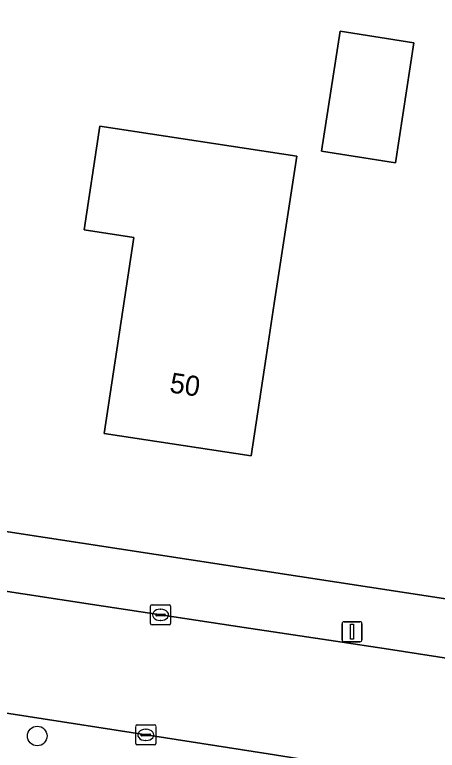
# Model space of a CAD drawing. Extents: x 161483 to 162250, y 379484 to 380833.
# Drawn here: x 161693.19 to 161714.27, y 380443.72 to 380480.35 of the extents above; entities that cross this region are included whole.
import ezdxf

# ---------------------------------------------------------------- set-up
doc = ezdxf.new("R2010")
doc.units = 0
for name, color, linetype in [('IMGEO_Boom', 7, 'Continuous'), ('IMGEO_Erf', 7, 'Continuous'), ('IMGEO_Kolk', 7, 'Continuous'), ('IMGEO_Lichtmast', 7, 'Continuous'), ('IMGEO_Pand', 7, 'Continuous'), ('IMGEO_Pand_nummerreeks', 7, 'Continuous'), ('IMGEO_Rijbaan_lokaal_open', 7, 'Continuous'), ('IMGEO_Voetpad_open', 7, 'Continuous')]:
    doc.layers.add(name, color=color, linetype=linetype)

msp = doc.modelspace()

# ---------------------------------------------------------------- linework, layer by layer
at = {"layer": 'IMGEO_Boom'}
msp.add_circle((161694.317, 380444.429), 0.489, dxfattribs=at)
at = {"layer": 'IMGEO_Erf'}
msp.add_lwpolyline([(161746.578, 380565.893), (161701.408, 380572.822), (161675.834, 380576.755), (161672.785, 380556.708), (161672.018, 380551.67), (161669.47, 380534.918), (161668.107, 380525.958), (161665.107, 380506.236), (161664.729, 380506.368), (161663.777, 380500), (161663.405, 380497.51), (161661.323, 380483.575), (161659.867, 380473.831), (161659.847, 380473.707), (161657.766, 380460.798), (161657.736, 380460.494), (161657.919, 380460.405), (161659.307, 380459.731), (161660.495, 380459.537), (161723.59, 380449.899)], dxfattribs=at)
for points in [[(161709.429, 380479.53), (161713.108, 380478.958), (161712.179, 380472.983), (161708.5, 380473.555)], [(161707.26, 380473.313), (161706.142, 380465.969), (161705.738, 380463.319), (161704.985, 380458.376), (161697.651, 380459.493), (161699.139, 380469.262), (161696.658, 380469.64), (161697.411, 380474.583), (161697.445, 380474.807)]]:
    msp.add_lwpolyline(points, close=True, dxfattribs=at)
at = {"layer": 'IMGEO_Kolk'}
for p, q in [((161699.968, 380450.036), (161699.968, 380450.888)), ((161700.043, 380450.962), (161700.895, 380450.962)), ((161700.969, 380450.888), (161700.969, 380450.036)), ((161700.227, 380450.456), (161700.227, 380450.468)), ((161700.665, 380450.419), (161700.267, 380450.419)), ((161700.27, 380450.505), (161700.668, 380450.505)), ((161700.456, 380450.742), (161700.481, 380450.742)), ((161700.711, 380450.468), (161700.711, 380450.456)), ((161700.479, 380450.182), (161700.454, 380450.182)), ((161700.895, 380449.962), (161700.043, 380449.962)), ((161699.231, 380444.058), (161699.231, 380444.91)), ((161699.306, 380444.984), (161700.158, 380444.984)), ((161700.232, 380444.91), (161700.232, 380444.058)), ((161699.719, 380444.764), (161699.744, 380444.764)), ((161699.49, 380444.478), (161699.49, 380444.49)), ((161699.928, 380444.441), (161699.53, 380444.441)), ((161699.533, 380444.527), (161699.931, 380444.527)), ((161699.742, 380444.204), (161699.717, 380444.204)), ((161699.974, 380444.49), (161699.974, 380444.478)), ((161700.158, 380443.984), (161699.306, 380443.984))]:
    msp.add_line(p, q, dxfattribs=at)
for points in [[(161699.968, 380450.036), (161699.968, 380450.888)], [(161700.043, 380450.962), (161700.895, 380450.962)], [(161700.969, 380450.888), (161700.969, 380450.036)], [(161700.895, 380449.962), (161700.043, 380449.962)], [(161699.231, 380444.058), (161699.231, 380444.91)], [(161699.306, 380444.984), (161700.158, 380444.984)], [(161700.232, 380444.91), (161700.232, 380444.058)], [(161700.158, 380443.984), (161699.306, 380443.984)]]:
    msp.add_lwpolyline(points, dxfattribs=at)
for centre, radius, start, end in [((161700.045, 380450.886), 0.0765, 91.552, 178.448), ((161700.045, 380450.886), 0.0765, 91.552, 178.448), ((161700.893, 380450.886), 0.0765, 1.552, 88.448), ((161700.893, 380450.886), 0.0765, 1.552, 88.448), ((161700.267, 380450.465), 0.0403, 85.8775, 175.7526), ((161700.264, 380450.455), 0.0366, 178.938, 274.7102), ((161700.668, 380450.462), 0.043, 264.8664, 352.4533), ((161700.672, 380450.467), 0.0386, 1.7309, 96.639), ((161700.045, 380450.038), 0.0765, 181.552, 268.448), ((161700.045, 380450.038), 0.0765, 181.552, 268.448), ((161700.893, 380450.038), 0.0765, 271.552, 358.448), ((161700.893, 380450.038), 0.0765, 271.552, 358.448), ((161699.308, 380444.908), 0.0765, 91.552, 178.448), ((161699.308, 380444.908), 0.0765, 91.552, 178.448), ((161700.156, 380444.908), 0.0765, 1.552, 88.448), ((161700.156, 380444.908), 0.0765, 1.552, 88.448), ((161699.53, 380444.487), 0.0403, 85.8775, 175.7526), ((161699.527, 380444.477), 0.0366, 178.938, 274.7102), ((161699.931, 380444.484), 0.043, 264.8664, 352.4533), ((161699.935, 380444.489), 0.0386, 1.7309, 96.639), ((161699.308, 380444.06), 0.0765, 181.552, 268.448), ((161699.308, 380444.06), 0.0765, 181.552, 268.448), ((161700.156, 380444.06), 0.0765, 271.552, 358.448), ((161700.156, 380444.06), 0.0765, 271.552, 358.448)]:
    msp.add_arc(centre, radius, start, end, dxfattribs=at)
for centre, major_axis, ratio, start_param, end_param in [((161700.455, 380450.462), (-0.387, 0.002), 0.722429, 4.712389, 7.853982), ((161700.48, 380450.462), (-0.39, 0.002), 0.717154, 1.570796, 4.712389), ((161699.718, 380444.484), (-0.387, 0.002), 0.722429, 4.712389, 7.853982), ((161699.743, 380444.484), (-0.39, 0.002), 0.717154, 1.570796, 4.712389)]:
    msp.add_ellipse(centre, major_axis=major_axis, ratio=ratio, start_param=start_param, end_param=end_param, dxfattribs=at)
at = {"layer": 'IMGEO_Lichtmast'}
for p, q in [((161709.623, 380450.121), (161710.413, 380450.121)), ((161710.413, 380450.121), (161709.623, 380450.121)), ((161709.523, 380449.221), (161709.523, 380450.021)), ((161709.523, 380450.021), (161709.523, 380449.221)), ((161710.513, 380450.021), (161710.513, 380449.221)), ((161710.513, 380449.221), (161710.513, 380450.021)), ((161710.413, 380449.121), (161709.623, 380449.121)), ((161709.623, 380449.121), (161710.413, 380449.121))]:
    msp.add_line(p, q, dxfattribs=at)
msp.add_lwpolyline([(161709.943, 380449.996), (161710.093, 380449.996), (161710.093, 380449.246), (161709.943, 380449.246), (161709.943, 380449.996)], dxfattribs=at)
for centre, start, end in [((161709.623, 380450.021), 90, 180), ((161709.623, 380450.021), 90, 180), ((161710.413, 380450.021), 0, 90), ((161710.413, 380450.021), 360, 90), ((161709.623, 380449.221), 180, 270), ((161709.623, 380449.221), 180, 270), ((161710.413, 380449.221), 270, 0), ((161710.413, 380449.221), 270, 0)]:
    msp.add_arc(centre, 0.1, start, end, dxfattribs=at)
at = {"layer": 'IMGEO_Pand'}
for points in [[(161709.429, 380479.53), (161708.5, 380473.555), (161712.179, 380472.983), (161713.108, 380478.958)], [(161707.26, 380473.313), (161697.445, 380474.807), (161697.411, 380474.583), (161696.658, 380469.64), (161699.139, 380469.262), (161697.651, 380459.493), (161704.985, 380458.376), (161705.738, 380463.319), (161706.142, 380465.969)]]:
    msp.add_lwpolyline(points, close=True, dxfattribs=at)
at = {"layer": 'IMGEO_Rijbaan_lokaal_open'}
for points in [[(161722.958, 380447.035), (161711.844, 380448.754), (161709.188, 380449.153), (161704.644, 380449.834), (161697.076, 380450.97), (161691.961, 380451.756)], [(161691.17, 380445.817), (161699.969, 380444.448), (161705.835, 380443.535), (161707.293, 380443.311), (161718.187, 380441.637), (161725.346, 380440.572), (161729.261, 380439.989), (161729.763, 380439.91), (161736.799, 380438.809), (161740.249, 380438.226), (161744.785, 380437.458), (161754.881, 380435.751)]]:
    msp.add_lwpolyline(points, dxfattribs=at)
at = {"layer": 'IMGEO_Voetpad_open'}
for points in [[(161727.758, 380449.302), (161723.59, 380449.899), (161660.495, 380459.537)], [(161659.625, 380456.642), (161660.774, 380456.435), (161669.297, 380455.18), (161681.29, 380453.395), (161687.434, 380452.451), (161691.961, 380451.756), (161697.076, 380450.97), (161704.644, 380449.834), (161709.188, 380449.153), (161711.844, 380448.754), (161722.958, 380447.035)], [(161754.881, 380435.751), (161744.785, 380437.458), (161740.249, 380438.226), (161736.799, 380438.809), (161729.763, 380439.91), (161729.261, 380439.989), (161725.346, 380440.572), (161718.187, 380441.637), (161707.293, 380443.311), (161705.835, 380443.535), (161699.969, 380444.448), (161691.17, 380445.817), (161690.732, 380442.772), (161764.511, 380431.266)]]:
    msp.add_lwpolyline(points, dxfattribs=at)

# ---------------------------------------------------------------- texts
at = {"layer": 'IMGEO_Pand_nummerreeks'}
msp.add_text('50', height=1, rotation=351.3402, dxfattribs=at).set_placement((161700.884, 380461.549))

doc.saveas('drawing.dxf')
